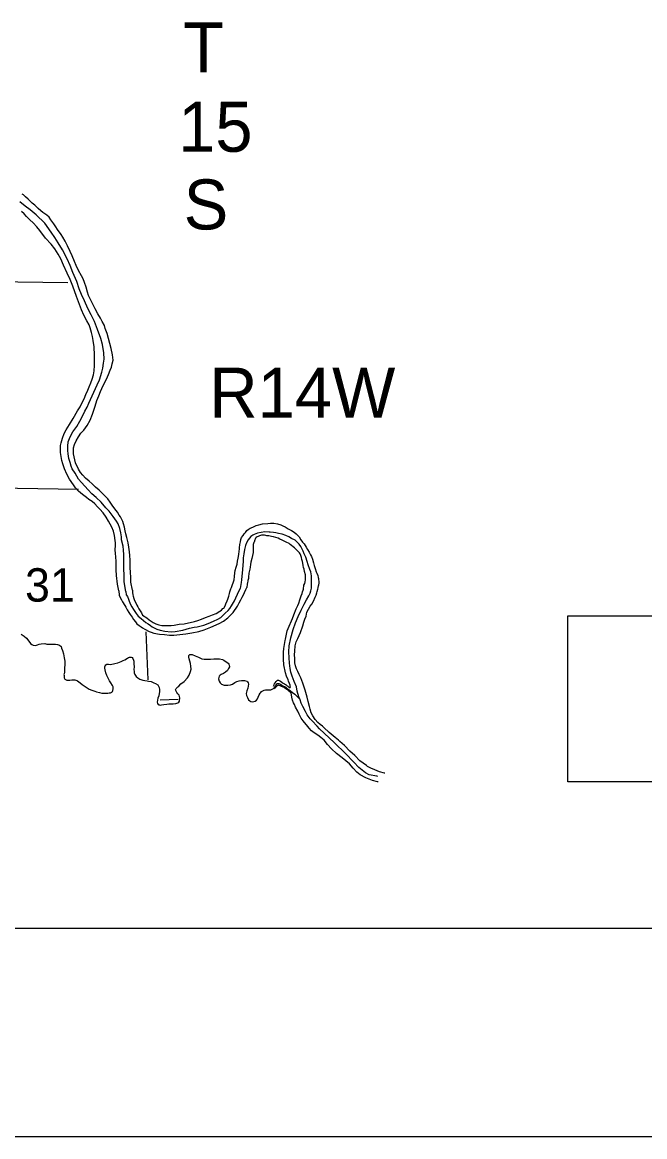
# Model space of a CAD drawing. Extents: x 369523 to 838377, y 495025 to 936819.
# Drawn here: x 735755 to 751512, y 495025 to 523245 of the extents above; entities that cross this region are included whole.
import ezdxf

# ---------------------------------------------------------------- set-up
doc = ezdxf.new("R2010")
doc.units = 0
for name, color, linetype in [('15', 7, 'Continuous'), ('21', 7, 'Continuous'), ('Level 10', 7, 'Continuous'), ('Level 15', 7, 'Continuous'), ('Level 22', 7, 'Continuous'), ('Level 6', 7, 'Continuous')]:
    doc.layers.add(name, color=color, linetype=linetype)

msp = doc.modelspace()

# ---------------------------------------------------------------- linework, layer by layer
at = {"layer": '15'}
for p, q in [((749569, 504011), (749569, 508211)), ((749569, 508211), (780521, 508211)), ((780521, 504011), (749569, 504011))]:
    msp.add_line(p, q, dxfattribs=at)
at = {"layer": '21'}
for p, q in [((740148, 520600), (740148, 520600)), ((558537, 500305), (833097, 500305)), ((838377, 495025), (542697, 495025))]:
    msp.add_line(p, q, dxfattribs=at)
at = {"layer": 'Level 10'}
for points in [[(735840, 518829), (735782, 518874), (735748, 518894)], [(738542, 508865), (738507, 509067), (738502, 509193), (738496, 509314), (738487, 509442), (738482, 509524), (738482, 509622), (738479, 509742), (738473, 509832), (738454, 509950), (738436, 510062), (738403, 510196), (738379, 510292), (738360, 510366), (738344, 510458), (738319, 510546), (738301, 510606), (738265, 510672), (738239, 510722), (738208, 510763), (738162, 510839), (738100, 510927), (738033, 511021), (737979, 511097), (737917, 511174), (737851, 511246), (737784, 511314), (737698, 511395), (737610, 511475), (737524, 511556), (737447, 511622), (737359, 511702), (737287, 511773), (737227, 511847), (737174, 511925), (737098, 512093), (737069, 512245), (737055, 512321), (737050, 512397), (737054, 512469), (737075, 512553), (737117, 512643), (737176, 512748), (737239, 512840), (737309, 512919), (737398, 513033), (737473, 513166), (737536, 513324), (737599, 513521), (737646, 513669), (737689, 513784), (737734, 513892), (737803, 514045), (737884, 514211), (737938, 514326), (737981, 514434), (738012, 514516), (738034, 514593), (738053, 514693), (738039, 514827), (738002, 514981), (737973, 515109), (737902, 515365), (737857, 515495), (737833, 515563), (737779, 515670), (737734, 515752), (737668, 515864), (737601, 515992), (737523, 516145), (737490, 516205), (737432, 516329), (737402, 516415), (737375, 516539), (737332, 516659), (737292, 516751), (737258, 516825), (737181, 516962), (737123, 517088), (737078, 517188), (737019, 517330), (736969, 517440), (736896, 517583), (736870, 517639), (736838, 517703), (736783, 517801), (736739, 517871), (736645, 517994), (736600, 518062), (736550, 518142), (736480, 518246), (736434, 518307), (736373, 518359), (736277, 518431), (736221, 518472), (736155, 518528), (736069, 518610), (736005, 518667), (735956, 518715), (735904, 518763), (735840, 518829)], [(738195, 508852), (738162, 509015), (738139, 509235), (738128, 509382), (738132, 509478), (738131, 509588), (738126, 509708), (738116, 509796), (738105, 509890), (738111, 509996), (738112, 510064), (738108, 510120), (738089, 510246), (738061, 510362), (738022, 510456), (737982, 510540), (737940, 510614), (737877, 510716), (737799, 510821), (737721, 510913), (737662, 510977), (737590, 511048), (737526, 511106), (737440, 511165), (737382, 511211), (737278, 511291), (737179, 511374), (737103, 511460), (737049, 511530), (736950, 511675), (736882, 511801), (736827, 511935), (736785, 512065), (736760, 512151), (736738, 512251), (736725, 512355), (736719, 512433), (736720, 512529), (736742, 512597), (736773, 512713), (736818, 512828), (736868, 512926), (736951, 513061), (737046, 513213), (737156, 513404), (737216, 513511), (737257, 513583), (737318, 513714), (737366, 513822), (737415, 513932), (737450, 514015), (737492, 514113), (737527, 514207), (737559, 514320), (737576, 514418), (737587, 514550), (737587, 514662), (737584, 514814), (737571, 515030), (737552, 515189), (737535, 515285), (737509, 515386), (737472, 515512), (737444, 515580), (737392, 515688), (737311, 515832), (737258, 515960), (737181, 516165), (737129, 516303), (737036, 516565), (736967, 516731), (736892, 516893), (736801, 517098), (736727, 517258), (736662, 517372), (736578, 517507), (736487, 517629), (736345, 517778), (736200, 517970), (736124, 518065), (736031, 518167), (735949, 518247), (735863, 518328), (735799, 518394), (735738, 518458)], [(741051, 508933), (741122, 509124), (741126, 509213), (741137, 509305), (741145, 509363), (741171, 509445), (741194, 509523), (741206, 509597), (741219, 509678), (741235, 509770), (741244, 509850), (741252, 509904), (741254, 509940), (741265, 510020), (741277, 510090), (741288, 510149), (741308, 510201), (741346, 510253), (741373, 510291), (741403, 510329), (741443, 510372), (741477, 510402), (741524, 510432), (741594, 510463), (741676, 510499), (741745, 510522), (741837, 510544), (741973, 510555), (742040, 510563), (742126, 510560), (742218, 510546), (742300, 510517), (742350, 510497), (742408, 510469), (742484, 510422), (742572, 510372), (742638, 510331), (742690, 510291), (742763, 510215), (742809, 510141), (742851, 510084), (742887, 510034), (742942, 509952), (742976, 509892), (743018, 509824), (743052, 509762), (743079, 509714), (743103, 509646), (743127, 509557), (743146, 509493), (743172, 509417), (743194, 509331), (743211, 509293), (743233, 509233), (743245, 509187), (743253, 509163), (743257, 509125), (743262, 509095), (743266, 509057), (743252, 508987)], [(742884, 508989), (742905, 509035), (742914, 509073), (742922, 509125), (742926, 509165), (742926, 509211), (742922, 509251), (742901, 509337), (742889, 509393), (742875, 509439), (742864, 509487), (742854, 509549), (742848, 509587), (742834, 509645), (742827, 509689), (742807, 509741), (742789, 509785), (742775, 509809), (742741, 509845), (742695, 509890), (742648, 509936), (742616, 509962), (742568, 509998), (742540, 510024), (742508, 510043), (742438, 510083), (742384, 510109), (742334, 510131), (742278, 510158), (742230, 510180), (742174, 510200), (742114, 510215), (742062, 510227), (741994, 510239), (741948, 510244), (741922, 510250), (741886, 510254), (741837, 510256), (741809, 510254), (741761, 510239), (741725, 510227), (741699, 510217), (741677, 510199), (741661, 510179), (741650, 510159), (741638, 510143), (741622, 510084), (741620, 510076), (741600, 510020), (741603, 509952), (741603, 509894), (741598, 509818), (741586, 509746), (741566, 509666), (741543, 509577), (741529, 509513), (741522, 509445), (741512, 509395), (741489, 509297), (741485, 509197), (741479, 509161), (741466, 509110), (741462, 509092), (741456, 509056), (741452, 509020), (741441, 508929)], [(738195, 508852), (738211, 508736), (738233, 508678), (738270, 508621), (738295, 508573), (738355, 508480), (738378, 508435), (738409, 508365), (738448, 508302), (738487, 508246), (738533, 508179), (738572, 508124), (738623, 508059), (738658, 508015), (738711, 507970), (738764, 507933), (738800, 507910), (738855, 507875), (738968, 507821), (739018, 507798), (739083, 507778), (739225, 507752), (739351, 507739), (739483, 507728), (739588, 507722), (739743, 507741), (739894, 507760), (740046, 507783), (740227, 507817), (740362, 507858), (740525, 507924), (740742, 508018), (740851, 508079), (740961, 508167), (741014, 508221), (741090, 508300), (741201, 508463), (741249, 508546), (741291, 508623), (741320, 508688), (741353, 508749), (741380, 508804), (741414, 508880), (741441, 508929)], [(738542, 508865), (738546, 508807), (738557, 508743), (738564, 508709), (738579, 508655), (738596, 508602), (738641, 508528), (738654, 508484), (738679, 508439), (738708, 508391), (738737, 508342), (738770, 508292), (738798, 508229), (738905, 508161), (738968, 508114), (739041, 508065), (739069, 508048), (739138, 508013), (739210, 507991), (739291, 507972), (739357, 507968), (739456, 507968), (739526, 507973), (739600, 507981), (739725, 508007), (739857, 508010), (740114, 508072), (740199, 508097), (740288, 508129), (740394, 508170), (740485, 508210), (740574, 508242), (740665, 508275), (740758, 508330), (740797, 508360), (740836, 508397), (740854, 508412), (740887, 508465), (740912, 508517), (740944, 508598), (740961, 508637), (740984, 508717), (741000, 508782), (741013, 508826), (741038, 508899), (741051, 508933)], [(742112, 506433), (742130, 506471), (742139, 506498), (742161, 506522), (742182, 506555), (742190, 506563), (742201, 506573), (742213, 506583), (742225, 506586), (742237, 506586), (742257, 506578), (742290, 506561), (742322, 506539), (742338, 506530), (742359, 506512), (742395, 506493), (742421, 506475), (742438, 506464), (742464, 506440), (742476, 506434), (742484, 506425), (742491, 506417), (742509, 506403), (742521, 506401), (742535, 506403), (742541, 506410), (742538, 506426), (742536, 506458), (742521, 506503), (742497, 506563), (742485, 506597), (742447, 506688), (742417, 506774), (742373, 506972), (742364, 507116), (742368, 507212), (742372, 507296), (742378, 507391), (742392, 507491), (742408, 507592), (742415, 507626), (742459, 507831), (742512, 507953), (742569, 508092), (742592, 508147), (742632, 508244), (742689, 508390), (742731, 508473), (742754, 508539), (742778, 508620), (742809, 508695), (742816, 508719), (742837, 508778), (742852, 508824), (742867, 508868), (742871, 508887), (742884, 508989)], [(743393, 505385), (743351, 505422), (743298, 505461), (743233, 505514), (743173, 505587), (743111, 505680), (743072, 505761), (743042, 505851), (743022, 505920), (742992, 506048), (742970, 506156), (742920, 506329), (742854, 506512), (742807, 506646), (742766, 506733), (742728, 506804), (742695, 506872), (742671, 506948), (742658, 507028), (742653, 507132), (742649, 507230), (742655, 507320), (742667, 507455), (742692, 507560), (742733, 507643), (742799, 507794), (742854, 507960), (742886, 508053), (742910, 508128), (742939, 508208), (742959, 508305), (743047, 508457), (743088, 508512), (743129, 508587), (743173, 508684), (743196, 508735), (743214, 508801), (743223, 508834), (743234, 508890), (743242, 508922), (743252, 508987)], [(744763, 504007), (744745, 504011), (744622, 504045), (744455, 504114), (744310, 504189), (744226, 504255), (744132, 504361), (744036, 504464), (743851, 504618), (743707, 504730), (743582, 504849), (743484, 504954), (743396, 505064), (743313, 505138), (743240, 505191), (743148, 505253), (743079, 505304), (743016, 505367), (742950, 505454), (742938, 505461), (742864, 505554), (742811, 505627), (742761, 505722), (742727, 505804), (742675, 505903), (742648, 505969), (742625, 506014), (742597, 506080), (742580, 506156), (742571, 506214), (742558, 506256), (742545, 506275), (742523, 506301), (742505, 506321), (742476, 506336), (742424, 506367), (742399, 506385), (742383, 506396), (742363, 506408), (742345, 506418), (742320, 506427), (742302, 506437), (742294, 506441), (742284, 506446), (742266, 506454), (742250, 506454), (742240, 506456), (742214, 506449), (742196, 506437), (742173, 506408), (742159, 506392), (742146, 506373), (742138, 506363)], [(744930, 504233), (744922, 504233), (744798, 504265), (744679, 504313), (744576, 504357), (744495, 504403), (744471, 504423), (744298, 504539), (744174, 504675), (744043, 504791), (743908, 504928), (743798, 505036), (743764, 505064), (743678, 505134), (743526, 505259), (743393, 505385)]]:
    msp.add_lwpolyline(points, dxfattribs=at)
at = {"layer": 'Level 15'}
msp.add_lwpolyline([(739242, 506091), (739701, 506101)], dxfattribs=at)
at = {"layer": 'Level 22'}
for points in [[(733728, 516701), (736910, 516660)], [(737179, 511411), (733554, 511469)], [(738941, 506596), (738895, 507807)]]:
    msp.add_lwpolyline(points, dxfattribs=at)
at = {"layer": 'Level 6'}
for points in [[(738380, 508828), (738348, 508976), (738335, 509084), (738333, 509186), (738334, 509279), (738326, 509369), (738325, 509491), (738328, 509635), (738329, 509765), (738319, 509879), (738308, 509983), (738264, 510139), (738263, 510213), (738247, 510317), (738222, 510423), (738182, 510541), (738143, 510609), (738057, 510731), (737958, 510862), (737870, 510952), (737748, 511091), (737625, 511211), (737519, 511302), (737419, 511406), (737338, 511497), (737252, 511591), (737182, 511679), (737139, 511752), (737091, 511826), (737017, 511938), (736990, 512008), (736964, 512094), (736936, 512200), (736913, 512316), (736909, 512402), (736908, 512510), (736917, 512620), (736966, 512748), (737032, 512875), (737133, 513010), (737210, 513142), (737275, 513271), (737340, 513401), (737395, 513502), (737441, 513598), (737648, 514062), (737709, 514190), (737766, 514385), (737793, 514489), (737812, 514615), (737824, 514718), (737817, 514878), (737784, 515082), (737741, 515238), (737662, 515465), (737585, 515667), (737498, 515837), (737416, 515999), (737333, 516188), (737252, 516348), (737198, 516498), (737133, 516684), (737032, 516913), (736963, 517085), (736892, 517257), (736769, 517485), (736665, 517662), (736578, 517796), (736483, 517931), (736323, 518155), (736108, 518366), (735954, 518495), (735829, 518592), (735693, 518696)], [(743080, 508991), (743073, 509232), (743057, 509330), (743038, 509388), (742992, 509510), (742968, 509594), (742929, 509700), (742895, 509787), (742864, 509851), (742828, 509923), (742804, 509969), (742762, 510027), (742705, 510085), (742661, 510130), (742573, 510174), (742505, 510214), (742431, 510249), (742331, 510281), (742239, 510298), (742175, 510314), (742114, 510324), (742032, 510333), (742006, 510337), (741892, 510342), (741806, 510328), (741709, 510305), (741621, 510277), (741589, 510260), (741541, 510224), (741508, 510184), (741476, 510140), (741435, 510063), (741409, 509997), (741380, 509893), (741366, 509789), (741349, 509680), (741343, 509598), (741338, 509490), (741319, 509298), (741313, 509222), (741308, 509126), (741300, 509063), (741289, 509005), (741269, 508907)], [(738380, 508828), (738384, 508750), (738421, 508707), (738441, 508639), (738460, 508583), (738493, 508504), (738525, 508440), (738568, 508375), (738619, 508302), (738634, 508272), (738691, 508209), (738761, 508148), (738822, 508096), (738881, 508047), (738939, 508010), (739000, 507971), (739047, 507936), (739093, 507907), (739158, 507878), (739242, 507852), (739361, 507828), (739523, 507813), (739629, 507820), (739818, 507856), (739991, 507901), (740106, 507924), (740178, 507935), (740347, 507979), (740460, 508023), (740592, 508082), (740705, 508133), (740782, 508174), (740890, 508279), (740964, 508349), (741007, 508404), (741050, 508467), (741127, 508591), (741157, 508669), (741207, 508767), (741269, 508907)], [(742717, 506307), (742694, 506413), (742635, 506556), (742583, 506683), (742551, 506787), (742537, 506883), (742516, 507013), (742513, 507149), (742506, 507301), (742515, 507456), (742554, 507659), (742612, 507865), (742672, 508040), (742739, 508200), (742818, 508358), (742894, 508510), (742954, 508622), (743008, 508725), (743042, 508790), (743061, 508848), (743078, 508913), (743079, 508941), (743080, 508991)], [(735724, 507754), (735804, 507696), (735858, 507648), (735919, 507574), (735959, 507518), (735995, 507486), (736027, 507468), (736087, 507465), (736137, 507479), (736183, 507495), (736232, 507506)], [(736232, 507506), (736326, 507511), (736376, 507494), (736410, 507497), (736467, 507494), (736505, 507498)], [(736505, 507498), (736596, 507501), (736647, 507488), (736697, 507473), (736738, 507438), (736751, 507398), (736776, 507337), (736801, 507255), (736818, 507153), (736833, 507067), (736831, 506977), (736823, 506899), (736823, 506790), (736816, 506748), (736810, 506732), (736815, 506706), (736818, 506670), (736818, 506646), (736831, 506610), (736879, 506583), (736919, 506586), (736959, 506587), (737011, 506590), (737045, 506593), (737081, 506595), (737133, 506580), (737151, 506571), (737190, 506547), (737219, 506518), (737269, 506479), (737375, 506405), (737446, 506362), (737514, 506330), (737589, 506307), (737635, 506292), (737707, 506271), (737770, 506259), (737832, 506256), (737878, 506255), (737923, 506258), (737957, 506261), (737985, 506265), (738019, 506284), (738036, 506302), (738050, 506327), (738059, 506367), (738052, 506415), (738039, 506447), (738000, 506518), (737965, 506565), (737896, 506702), (737871, 506770), (737853, 506846), (737848, 506886), (737848, 506922), (737853, 506950), (737874, 506977), (737896, 506993), (737912, 506991), (737938, 506988), (737990, 506983), (738100, 507009), (738173, 507025), (738256, 507057), (738306, 507080), (738353, 507103), (738415, 507140), (738444, 507161), (738470, 507169), (738514, 507166), (738538, 507161), (738538, 507159), (738551, 507137), (738571, 507095), (738578, 507063), (738581, 506997), (738583, 506921), (738580, 506853), (738583, 506809), (738590, 506769), (738601, 506729), (738638, 506682), (738681, 506642), (738727, 506609), (738806, 506587), (738858, 506576), (738914, 506565), (738954, 506558), (739018, 506549), (739083, 506522), (739127, 506501), (739184, 506468), (739205, 506433), (739217, 506403), (739226, 506351), (739232, 506291), (739223, 506251), (739210, 506186), (739189, 506128), (739176, 506081), (739173, 506027)], [(739173, 506027), (739180, 505993), (739198, 505971), (739211, 505962), (739225, 505958), (739243, 505952), (739279, 505959), (739336, 505972), (739414, 505980), (739464, 505987), (739526, 505988), (739576, 505989), (739638, 505997), (739689, 506008), (739721, 506026), (739736, 506055), (739741, 506137), (739723, 506203), (739696, 506242), (739670, 506272), (739655, 506294), (739641, 506321), (739636, 506341), (739652, 506378), (739695, 506413), (739714, 506435), (739769, 506489), (739852, 506556), (739940, 506644), (739976, 506711), (740012, 506806), (740027, 506863), (740020, 506941), (740012, 507007), (739995, 507065), (739980, 507124), (739969, 507166), (739970, 507208), (739978, 507223), (739997, 507235), (740013, 507235), (740053, 507232), (740128, 507202), (740219, 507164), (740253, 507150), (740299, 507125), (740362, 507116), (740437, 507120), (740521, 507116), (740605, 507123), (740663, 507129), (740745, 507124), (740823, 507108), (740856, 507092), (740888, 507071), (740929, 507042), (740939, 507034), (740965, 507019), (740984, 506993), (740992, 506973), (740997, 506923), (740978, 506881), (740951, 506830), (740898, 506785), (740845, 506755), (740789, 506732), (740766, 506714), (740742, 506683), (740726, 506617), (740741, 506563), (740764, 506517), (740796, 506486), (740867, 506459), (740955, 506457), (741023, 506466), (741078, 506488), (741139, 506525), (741183, 506548), (741242, 506569), (741302, 506580), (741332, 506579), (741384, 506576), (741438, 506563), (741459, 506542), (741471, 506520), (741480, 506484), (741475, 506432), (741464, 506387), (741437, 506319), (741423, 506252), (741432, 506200), (741453, 506149), (741482, 506091), (741515, 506060), (741545, 506044), (741585, 506037), (741649, 506052), (741684, 506077), (741708, 506110), (741727, 506152), (741755, 506215)], [(741755, 506215), (741776, 506253), (741794, 506274), (741815, 506302), (741843, 506319), (741861, 506327), (741879, 506334), (741915, 506341), (741947, 506341), (741957, 506341), (741991, 506338), (742021, 506337), (742046, 506339), (742068, 506350), (742098, 506366), (742114, 506377), (742141, 506403), (742166, 506438), (742176, 506454), (742201, 506489), (742213, 506501), (742237, 506504), (742247, 506502), (742295, 506481), (742316, 506467), (742332, 506453), (742425, 506405), (742470, 506368), (742536, 506325), (742599, 506275), (742652, 506231), (742782, 506101)], [(744752, 504146), (744730, 504151), (744533, 504189), (744442, 504240), (744278, 504376), (744145, 504512), (743941, 504732), (743657, 504997), (743525, 505127), (743280, 505350), (743219, 505421), (743096, 505559), (743039, 505610), (742969, 505711), (742921, 505792), (742855, 505923), (742819, 506004), (742787, 506088), (742760, 506162), (742717, 506307)]]:
    msp.add_lwpolyline(points, dxfattribs=at)

# ---------------------------------------------------------------- texts
at = {"layer": '21'}
for s, height, p in [('T', 1267, (739825, 521978)), ('15', 1267.2, (739699, 519966)), ('S', 1267, (739840, 517999)), ('R14W', 1267.2, (740490, 513232))]:
    msp.add_text(s, height=height, dxfattribs=at).set_placement(p)
at = {"layer": 'Level 22'}
msp.add_text('31', height=844.8, dxfattribs=at).set_placement((735825, 508575))

doc.saveas('drawing.dxf')
